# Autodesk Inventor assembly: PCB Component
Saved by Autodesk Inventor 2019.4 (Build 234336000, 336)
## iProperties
Created: 2020-01
Part Number: PCB Component
Document SubType Name: Assembly
Designer: Administrator
Title: PCB Component
Author: Administrator
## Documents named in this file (4)
- c:\worker\convert-fusion-r01\tmp\job-1\61\output\files\aee60a31-d91c-4752-9293-a14cfbf1decc\PCB Component.iam
- c:\worker\convert-fusion-r01\tmp\job-1\61\output\files\aee60a31-d91c-4752-9293-a14cfbf1decc\Board.ipt
- c:\worker\convert-fusion-r01\tmp\job-1\61\output\files\aee60a31-d91c-4752-9293-a14cfbf1decc\1X03.ipt
- c:\worker\convert-fusion-r01\tmp\job-1\61\output\files\aee60a31-d91c-4752-9293-a14cfbf1decc\1X06.ipt
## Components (3 placed, 3 different names)
1. Board:1
2. 1X03:JP1
3. 1X06:PO1
